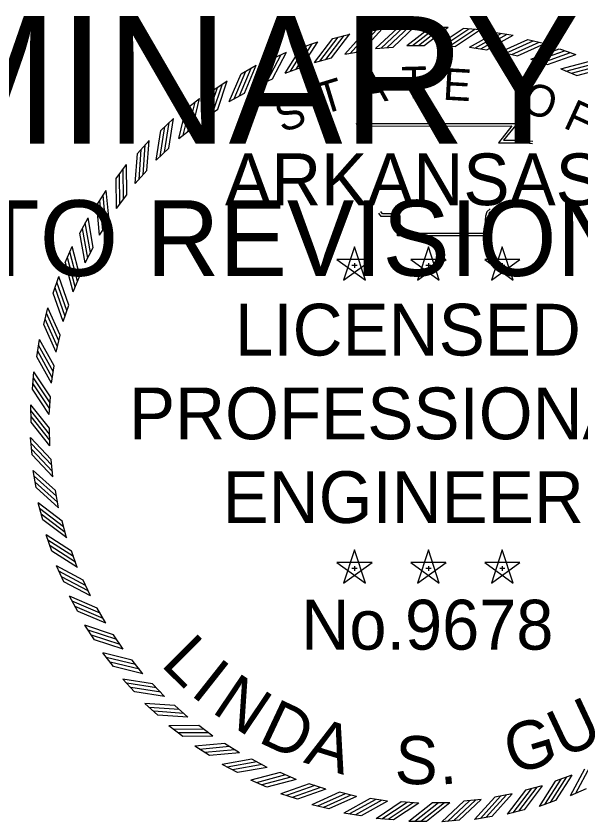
# Model space of a CAD drawing. Extents: x 0 to 1228740, y 0 to 152440.
# Drawn here: x 30.812 to 32.511, y 17.868 to 20.292 of the extents above; entities that cross this region are included whole.
import ezdxf

# ---------------------------------------------------------------- set-up
doc = ezdxf.new("R2010")
doc.units = 0
doc.layers.add('R_Draft', color=7, linetype='Continuous')
doc.layers.add('STAMP', color=7, linetype='Continuous')

msp = doc.modelspace()

# ---------------------------------------------------------------- linework, layer by layer
at = {"layer": 'STAMP'}
for p, q in [((31.8616, 20.2442), (31.9132, 20.2533)), ((31.9597, 20.2559), (32.0118, 20.2607)), ((32.0589, 20.2588), (32.1113, 20.2588)), ((32.157, 20.2549), (32.2093, 20.251)), ((32.255, 20.2421), (32.3068, 20.234)), ((31.67, 20.1967), (31.7194, 20.2141)), ((31.7648, 20.2244), (31.8155, 20.2377)), ((32.3516, 20.2214), (32.4025, 20.209)), ((31.8936, 20.1938), (31.9459, 20.1986)), ((31.9874, 20.203), (32.0399, 20.203)), ((32.0816, 20.2045), (32.134, 20.2006)), ((32.1757, 20.1982), (32.2276, 20.19)), ((32.4461, 20.1927), (32.4958, 20.1762)), ((31.5778, 20.1612), (31.6256, 20.1827)), ((31.7098, 20.1523), (31.7606, 20.1656)), ((31.8008, 20.1768), (31.8526, 20.1859)), ((32.2689, 20.1841), (32.3199, 20.1717)), ((31.4888, 20.1183), (31.5347, 20.1437)), ((32.3606, 20.1624), (32.4105, 20.1458)), ((31.6212, 20.1203), (31.6707, 20.1378)), ((32.4503, 20.1332), (32.4986, 20.1125)), ((31.4037, 20.0682), (31.4473, 20.0972)), ((31.5354, 20.0811), (31.5833, 20.1026)), ((31.4532, 20.0349), (31.4992, 20.0603)), ((31.323, 20.0112), (31.3641, 20.0438)), ((31.3751, 19.9821), (31.4188, 20.0112)), ((31.2473, 19.9477), (31.2855, 19.9836)), ((31.3016, 19.9231), (31.3428, 19.9557)), ((31.1771, 19.8782), (31.2122, 19.9171)), ((31.2333, 19.8581), (31.2716, 19.8941)), ((31.1129, 19.8032), (31.1447, 19.8448)), ((31.1705, 19.7878), (31.2057, 19.8268)), ((31.0551, 19.7231), (31.0833, 19.7672)), ((31.1138, 19.7125), (31.1457, 19.7543)), ((31.0041, 19.6385), (31.0286, 19.6848)), ((31.0635, 19.6328), (31.0918, 19.677)), ((30.9602, 19.55), (30.9808, 19.5982)), ((31.0199, 19.5492), (31.0445, 19.5956)), ((31.8299, 19.5976), (31.7971, 19.497)), ((31.8626, 19.4971), (31.83, 19.5977)), ((32.0522, 19.5976), (32.0194, 19.497)), ((32.0848, 19.4971), (32.0522, 19.5977)), ((32.2745, 19.5976), (32.2417, 19.497)), ((32.3071, 19.4971), (32.2745, 19.5977)), ((31.8827, 19.5592), (31.777, 19.5593)), ((31.7771, 19.5592), (31.8626, 19.497)), ((31.7972, 19.4971), (31.8829, 19.5592)), ((32.105, 19.5592), (31.9992, 19.5593)), ((31.9993, 19.5592), (32.0849, 19.497)), ((32.0195, 19.4971), (32.1052, 19.5592)), ((32.3273, 19.5592), (32.2215, 19.5593)), ((32.2216, 19.5592), (32.3071, 19.497)), ((32.2418, 19.4971), (32.3274, 19.5592)), ((31.8224, 19.5423), (31.8381, 19.5423)), ((31.83, 19.548), (31.83, 19.5347)), ((32.0446, 19.5423), (32.0604, 19.5423)), ((32.0523, 19.548), (32.0523, 19.5347)), ((32.2669, 19.5423), (32.2826, 19.5423)), ((32.2746, 19.548), (32.2746, 19.5347)), ((30.9239, 19.4581), (30.9404, 19.5079)), ((30.9834, 19.4623), (31.004, 19.5106)), ((30.8952, 19.3636), (30.9076, 19.4145)), ((30.9542, 19.3727), (30.9708, 19.4225)), ((30.8744, 19.267), (30.8826, 19.3188)), ((30.9325, 19.2809), (30.9449, 19.332)), ((30.8617, 19.1691), (30.8656, 19.2213)), ((30.9184, 19.1877), (30.9266, 19.2396)), ((30.9121, 19.0937), (30.9159, 19.146)), ((30.8571, 19.0704), (30.8566, 19.1228)), ((30.9135, 18.9994), (30.9131, 19.0519)), ((30.8607, 18.9717), (30.8559, 19.0239)), ((30.9228, 18.9056), (30.918, 18.9579)), ((30.8724, 18.8736), (30.8633, 18.9252)), ((30.9398, 18.8129), (30.9306, 18.8646)), ((30.8922, 18.7768), (30.8789, 18.8275)), ((30.9643, 18.7218), (30.951, 18.7726)), ((30.9199, 18.682), (30.9024, 18.7314)), ((30.9963, 18.6332), (30.9788, 18.6827)), ((31.8299, 18.6862), (31.7971, 18.5857)), ((31.8626, 18.5857), (31.83, 18.6864)), ((32.0522, 18.6862), (32.0194, 18.5857)), ((32.0848, 18.5857), (32.0522, 18.6864)), ((32.2745, 18.6862), (32.2417, 18.5857)), ((32.3071, 18.5857), (32.2745, 18.6864)), ((31.8827, 18.6478), (31.777, 18.6479)), ((31.7771, 18.6478), (31.8626, 18.5856)), ((31.7972, 18.5857), (31.8829, 18.6478)), ((32.105, 18.6478), (31.9992, 18.6479)), ((31.9993, 18.6478), (32.0849, 18.5856)), ((32.0195, 18.5857), (32.1052, 18.6478)), ((32.3273, 18.6478), (32.2215, 18.6479)), ((32.2216, 18.6478), (32.3071, 18.5856)), ((32.2418, 18.5857), (32.3274, 18.6478)), ((30.9553, 18.5898), (30.9339, 18.6376)), ((31.8224, 18.6309), (31.8381, 18.6309)), ((31.83, 18.6366), (31.83, 18.6233)), ((32.0446, 18.6309), (32.0604, 18.6309)), ((32.0523, 18.6366), (32.0523, 18.6233)), ((32.2669, 18.6309), (32.2826, 18.6309)), ((32.2746, 18.6366), (32.2746, 18.6233)), ((31.0355, 18.5474), (31.014, 18.5954)), ((30.9983, 18.5008), (30.9729, 18.5467)), ((31.0817, 18.4653), (31.0563, 18.5112)), ((31.0484, 18.4157), (31.0193, 18.4593)), ((31.1345, 18.3871), (31.1053, 18.4309)), ((31.1054, 18.335), (31.0728, 18.3761)), ((31.1935, 18.3137), (31.1609, 18.3548)), ((31.1688, 18.2593), (31.133, 18.2976)), ((31.2584, 18.2453), (31.2225, 18.2836)), ((31.2383, 18.1891), (31.1995, 18.2243)), ((31.3288, 18.1826), (31.2898, 18.2178)), ((31.3134, 18.1249), (31.2717, 18.1567)), ((31.4041, 18.1258), (31.3623, 18.1577)), ((31.3935, 18.0671), (31.3494, 18.0954)), ((31.4838, 18.0755), (31.4395, 18.1038)), ((31.4781, 18.0161), (31.4318, 18.0406)), ((31.5674, 18.0319), (31.521, 18.0565)), ((31.6543, 17.9954), (31.606, 18.0161)), ((32.4834, 18.0083), (32.4339, 17.9908)), ((31.5666, 17.9723), (31.5184, 17.9929)), ((31.7439, 17.9662), (31.6941, 17.9828)), ((32.3947, 17.9763), (32.3439, 17.963)), ((32.5268, 17.9674), (32.479, 17.9459)), ((31.6584, 17.9359), (31.6087, 17.9524)), ((31.8356, 17.9445), (31.7846, 17.9569)), ((31.9289, 17.9304), (31.877, 17.9386)), ((32.3037, 17.9518), (32.252, 17.9427)), ((31.753, 17.9072), (31.7021, 17.9196)), ((32.0229, 17.9241), (31.9705, 17.928)), ((32.1172, 17.9256), (32.0647, 17.9251)), ((32.211, 17.9348), (32.1587, 17.93)), ((32.4346, 17.9319), (32.3852, 17.9145)), ((31.8495, 17.8865), (31.7978, 17.8946)), ((32.3398, 17.9042), (32.2891, 17.8909)), ((31.9475, 17.8737), (31.8952, 17.8776)), ((32.0462, 17.8692), (31.9938, 17.8687)), ((32.1449, 17.8727), (32.0927, 17.8679)), ((32.243, 17.8844), (32.1914, 17.8753))]:
    msp.add_line(p, q, dxfattribs=at)
for points in [[(31.8008, 20.1768), (31.8615, 20.2441)], [(31.8174, 20.1795), (31.8781, 20.2469)], [(31.8353, 20.1831), (31.896, 20.2504)], [(31.8525, 20.186), (31.9132, 20.2533)], [(31.8935, 20.1937), (31.9596, 20.2558)], [(31.9103, 20.1951), (31.9764, 20.2572)], [(31.9284, 20.1972), (31.9945, 20.2593)], [(31.9458, 20.1986), (32.0119, 20.2607)], [(31.9873, 20.203), (32.0588, 20.2587)], [(32.0042, 20.2028), (32.0757, 20.2586)], [(32.0224, 20.2032), (32.0939, 20.259)], [(32.0398, 20.2031), (32.1113, 20.2588)], [(32.0816, 20.2045), (32.157, 20.2548)], [(32.0984, 20.2031), (32.1738, 20.2534)], [(32.1166, 20.2021), (32.192, 20.2525)], [(32.134, 20.2007), (32.2094, 20.2511)], [(32.1756, 20.1981), (32.2549, 20.2421)], [(32.1923, 20.1954), (32.2716, 20.2393)], [(31.6706, 20.1378), (31.7194, 20.2142)], [(31.7098, 20.1522), (31.7647, 20.2243)], [(31.7261, 20.1563), (31.7811, 20.2285)], [(31.7436, 20.1614), (31.7986, 20.2335)], [(31.7606, 20.1656), (31.8155, 20.2378)], [(32.2103, 20.1929), (32.2896, 20.2369)], [(32.2275, 20.1901), (32.3068, 20.234)], [(32.2688, 20.1841), (32.3515, 20.2214)], [(32.2852, 20.1799), (32.3678, 20.2172)], [(31.6211, 20.1202), (31.6699, 20.1966)], [(31.6371, 20.1257), (31.6859, 20.2021)], [(31.6541, 20.1321), (31.7029, 20.2085)], [(32.303, 20.176), (32.3856, 20.2133)], [(32.3199, 20.1717), (32.4026, 20.209)], [(32.3606, 20.1624), (32.446, 20.1927)], [(31.5508, 20.0878), (31.5932, 20.1679)], [(31.5673, 20.0956), (31.6096, 20.1758)], [(31.5833, 20.1026), (31.6256, 20.1828)], [(32.3765, 20.1569), (32.462, 20.1872)], [(32.3939, 20.1515), (32.4794, 20.1818)], [(32.4104, 20.1459), (32.4959, 20.1762)], [(31.4991, 20.0603), (31.5347, 20.1437)], [(31.5354, 20.081), (31.5777, 20.1612)], [(32.4502, 20.1332), (32.5379, 20.1563)], [(32.4656, 20.1264), (32.5533, 20.1495)], [(32.4825, 20.1196), (32.5702, 20.1428)], [(31.4532, 20.0348), (31.4888, 20.1182)], [(31.468, 20.0429), (31.5036, 20.1263)], [(31.4838, 20.052), (31.5193, 20.1354)], [(32.4985, 20.1126), (32.5862, 20.1357)], [(31.4188, 20.0112), (31.4473, 20.0973)], [(31.3892, 19.9913), (31.4178, 20.0773)], [(31.4041, 20.0017), (31.4327, 20.0878)], [(31.3751, 19.982), (31.4037, 20.0681)], [(31.3149, 19.9333), (31.3363, 20.0215)], [(31.3289, 19.945), (31.3503, 20.0331)], [(31.3427, 19.9557), (31.3641, 20.0438)], [(31.3016, 19.923), (31.323, 20.0111)], [(31.2587, 19.8822), (31.2727, 19.9718)], [(31.2715, 19.8941), (31.2855, 19.9836)], [(31.2333, 19.8581), (31.2473, 19.9476)], [(31.2457, 19.8695), (31.2597, 19.9591)], [(31.8637, 19.9081), (31.8357, 19.9686), (32.319, 19.9688), (32.2786, 19.9181), (32.3115, 19.9185), (32.3389, 19.9189), (32.3663, 19.9159)], [(31.8706, 19.9113), (31.8477, 19.9609), (32.3031, 19.9612), (32.2626, 19.9102), (32.3116, 19.9109), (32.3385, 19.9112), (32.3655, 19.9083)], [(31.1939, 19.8139), (31.2004, 19.9043)], [(31.2057, 19.8267), (31.2122, 19.9172)], [(31.1705, 19.7877), (31.1771, 19.8782)], [(31.1819, 19.8001), (31.1885, 19.8906)], [(31.1349, 19.7405), (31.134, 19.8311)], [(31.1456, 19.7542), (31.1447, 19.8449)], [(31.1138, 19.7124), (31.1129, 19.8031)], [(31.1242, 19.7257), (31.1232, 19.8164)], [(31.0917, 19.677), (31.0833, 19.7673)], [(31.0727, 19.6468), (31.0643, 19.7371)], [(31.0822, 19.6624), (31.0738, 19.7527)], [(31.0635, 19.6327), (31.0551, 19.723)], [(32.2429, 19.7055), (32.2346, 19.6988), (32.2319, 19.6888), (32.2291, 19.6638), (32.2291, 19.6303), (31.9594, 19.6303), (31.9594, 19.6754), (31.9594, 19.6855), (31.9484, 19.6888), (31.91, 19.6888), (31.9032, 19.6992)], [(32.238, 19.7115), (32.2279, 19.7032), (32.2243, 19.6902), (32.2215, 19.6642), (32.2215, 19.638), (31.967, 19.638), (31.967, 19.6754), (31.967, 19.6911), (31.9496, 19.6965), (31.9142, 19.6965), (31.9096, 19.7034)], [(31.0444, 19.5956), (31.0286, 19.6849)], [(31.0361, 19.5802), (31.0203, 19.6695)], [(31.0199, 19.5491), (31.0041, 19.6384)], [(31.0279, 19.564), (31.0121, 19.6532)], [(31.004, 19.5105), (30.9808, 19.5982)], [(30.9902, 19.4777), (30.967, 19.5653)], [(30.997, 19.4946), (30.9738, 19.5822)], [(30.9834, 19.4622), (30.9603, 19.5499)], [(30.965, 19.4059), (30.9347, 19.4914)], [(30.9707, 19.4225), (30.9404, 19.5079)], [(30.9597, 19.3885), (30.9294, 19.474)], [(30.9542, 19.3726), (30.9239, 19.458)], [(30.9448, 19.3319), (30.9076, 19.4146)], [(30.9405, 19.315), (30.9033, 19.3977)], [(30.9366, 19.2972), (30.8994, 19.3799)], [(30.9325, 19.2809), (30.8952, 19.3635)], [(30.9265, 19.2396), (30.8826, 19.3189)], [(30.9236, 19.2223), (30.8797, 19.3016)], [(30.9212, 19.2043), (30.8772, 19.2836)], [(30.9184, 19.1877), (30.8745, 19.267)], [(30.9159, 19.146), (30.8655, 19.2214)], [(30.9144, 19.1286), (30.8641, 19.204)], [(30.9135, 19.1104), (30.8631, 19.1858)], [(30.9121, 19.0936), (30.8618, 19.169)], [(30.913, 19.0519), (30.8566, 19.1228)], [(30.913, 19.0344), (30.8566, 19.1054)], [(30.9136, 19.0162), (30.8572, 19.0872)], [(30.9136, 18.9993), (30.8572, 19.0703)], [(30.9179, 18.9578), (30.8559, 19.0239)], [(30.9194, 18.9404), (30.8573, 19.0065)], [(30.9215, 18.9223), (30.8594, 18.9884)], [(30.9228, 18.9055), (30.8608, 18.9716)], [(30.9306, 18.8645), (30.8633, 18.9252)], [(30.9335, 18.8473), (30.8662, 18.908)], [(30.937, 18.8294), (30.8697, 18.8902)], [(30.9398, 18.8128), (30.8725, 18.8735)], [(30.9509, 18.7726), (30.8788, 18.8275)], [(30.9552, 18.7557), (30.8831, 18.8106)], [(30.9602, 18.7382), (30.8881, 18.7931)], [(30.9644, 18.7218), (30.8923, 18.7768)], [(30.9788, 18.6826), (30.9024, 18.7314)], [(30.9845, 18.6661), (30.908, 18.7149)], [(30.9909, 18.6491), (30.9145, 18.6979)], [(30.9964, 18.6331), (30.92, 18.682)], [(31.014, 18.5953), (30.9338, 18.6376)], [(31.021, 18.5793), (30.9408, 18.6216)], [(31.0288, 18.5629), (30.9486, 18.6052)], [(31.0356, 18.5474), (30.9554, 18.5898)], [(31.0563, 18.5111), (30.9729, 18.5467)], [(31.0646, 18.4958), (30.9812, 18.5314)], [(31.0737, 18.4801), (30.9903, 18.5156)], [(31.0818, 18.4652), (30.9984, 18.5008)], [(31.1053, 18.4308), (31.0193, 18.4593)], [(31.1149, 18.4162), (31.0288, 18.4447)], [(31.1253, 18.4012), (31.0393, 18.4298)], [(31.1345, 18.3871), (31.0485, 18.4157)], [(31.1609, 18.3547), (31.0728, 18.3761)], [(31.1716, 18.341), (31.0835, 18.3623)], [(31.1832, 18.327), (31.0951, 18.3483)], [(31.1936, 18.3136), (31.1055, 18.335)], [(31.2225, 18.2836), (31.1329, 18.2976)], [(31.2343, 18.2707), (31.1448, 18.2847)], [(31.2471, 18.2577), (31.1575, 18.2717)], [(31.2585, 18.2453), (31.1689, 18.2593)], [(31.2898, 18.2177), (31.1994, 18.2243)], [(31.3027, 18.2059), (31.2122, 18.2124)], [(31.3165, 18.194), (31.226, 18.2005)], [(31.3289, 18.1826), (31.2384, 18.1891)], [(31.3623, 18.1576), (31.2717, 18.1567)], [(31.3761, 18.1469), (31.2855, 18.146)], [(31.3908, 18.1362), (31.3002, 18.1353)], [(31.4041, 18.1258), (31.3135, 18.1249)], [(31.4396, 18.1038), (31.3493, 18.0953)], [(31.4542, 18.0942), (31.3639, 18.0858)], [(31.4697, 18.0847), (31.3795, 18.0763)], [(31.4839, 18.0755), (31.3936, 18.0671)], [(31.521, 18.0564), (31.4317, 18.0406)], [(31.5363, 18.0481), (31.4471, 18.0323)], [(31.5526, 18.04), (31.4633, 18.0241)], [(32.5373, 18.033), (32.4949, 17.9528)], [(31.5675, 18.0319), (31.4782, 18.0161)], [(31.606, 18.016), (31.5184, 17.9929)], [(31.622, 18.009), (31.5344, 17.9858)], [(32.4834, 18.0084), (32.4346, 17.932)], [(32.5213, 18.026), (32.479, 17.9458)], [(31.6389, 18.0022), (31.5512, 17.9791)], [(31.6544, 17.9954), (31.5667, 17.9723)], [(32.434, 17.9908), (32.3851, 17.9144)], [(32.4505, 17.9965), (32.4016, 17.9201)], [(32.4675, 18.0029), (32.4187, 17.9265)], [(31.6941, 17.9827), (31.6087, 17.9524)], [(31.7106, 17.9771), (31.6252, 17.9468)], [(31.728, 17.9717), (31.6426, 17.9414)], [(31.744, 17.9662), (31.6585, 17.9359)], [(32.344, 17.963), (32.289, 17.8908)], [(32.3609, 17.9672), (32.306, 17.8951)], [(32.3784, 17.9723), (32.3235, 17.9002)], [(32.3948, 17.9764), (32.3398, 17.9043)], [(31.7847, 17.9569), (31.702, 17.9196)], [(31.8016, 17.9526), (31.7189, 17.9153)], [(31.8194, 17.9487), (31.7367, 17.9114)], [(31.8357, 17.9445), (31.7531, 17.9072)], [(31.877, 17.9385), (31.7977, 17.8946)], [(31.8942, 17.9357), (31.8149, 17.8917)], [(32.2521, 17.9426), (32.1913, 17.8753)], [(32.2693, 17.9455), (32.2085, 17.8782)], [(32.2871, 17.9491), (32.2264, 17.8817)], [(32.3038, 17.9518), (32.243, 17.8845)], [(31.9123, 17.9332), (31.833, 17.8893)], [(31.9289, 17.9305), (31.8496, 17.8865)], [(31.9706, 17.9279), (31.8952, 17.8775)], [(31.988, 17.9265), (31.9126, 17.8761)], [(32.0062, 17.9255), (31.9308, 17.8752)], [(32.023, 17.9241), (31.9476, 17.8738)], [(32.0647, 17.925), (31.9937, 17.8686)], [(32.0822, 17.925), (32.0112, 17.8686)], [(32.1004, 17.9256), (32.0294, 17.8692)], [(32.1172, 17.9256), (32.0463, 17.8692)], [(32.1587, 17.93), (32.0927, 17.8679)], [(32.1761, 17.9314), (32.1101, 17.8693)], [(32.1942, 17.9335), (32.1282, 17.8714)], [(32.211, 17.9349), (32.145, 17.8728)]]:
    msp.add_lwpolyline(points, dxfattribs=at)

# ---------------------------------------------------------------- texts
at = {"layer": 'R_Draft'}
for s, height, p in [('PRELIMINARY', 0.3836, (29.0289, 19.908)), ('SUBJECT TO REVISION', 0.227432, (29.2271, 19.5102))]:
    msp.add_text(s, height=height, rotation=0, dxfattribs=at).set_placement(p)
at = {"layer": 'STAMP'}
for s, height, rotation, p in [('A', 0.0953, 8.6788, (31.8489, 20.0244)), ('T', 0.0953, 1.4789, (31.972, 20.0434)), ('E', 0.0953, 356.672, (32.094, 20.0405)), ('T', 0.0953, 16.9015, (31.7332, 19.9942)), ('O', 0.0953, 341.2218, (32.3255, 20.0078)), ('S', 0.0953, 19.7726, (31.6119, 19.9398)), ('F', 0.0953, 335.3628, (32.454, 19.9576)), ('L', 0.1448, 315.1295, (31.2447, 18.3399)), ('I', 0.1448, 321.696, (31.3328, 18.2523)), ('N', 0.1448, 326.0736, (31.3968, 18.1997)), ('D', 0.1448, 334.8288, (31.536, 18.1099)), ('U', 0.1448, 25.1712, (32.4571, 18.0571)), ('G', 0.1448, 16.7808, (32.3059, 18.0089)), ('A', 0.1448, 342.8544, (31.6742, 18.0471)), ('S', 0.1448, 357.8112, (31.9493, 17.9838)), ('.', 0.1448, 5.1072, (32.0873, 17.9795))]:
    msp.add_text(s, height=height, rotation=rotation, dxfattribs=at).set_placement(p)
for s, height, p in [('ARKANSAS', 0.15559, (31.4406, 19.7229)), ('LICENSED', 0.15559, (31.4703, 19.2707)), ('PROFESSIONAL', 0.155594, (31.1517, 19.0188)), ('ENGINEER', 0.15559, (31.4332, 18.7669)), ('No.9678', 0.15004, (31.6697, 18.386))]:
    msp.add_text(s, height=height, dxfattribs=at).set_placement(p)

doc.saveas('drawing.dxf')
